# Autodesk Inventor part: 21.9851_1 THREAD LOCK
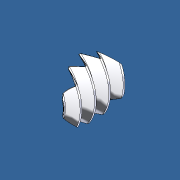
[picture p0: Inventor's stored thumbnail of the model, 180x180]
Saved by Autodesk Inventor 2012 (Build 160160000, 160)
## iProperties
Created: 2014-01
Part Number: 21.9851_1 THREAD LOCK
Material: Nylon-6/6
Document SubType Name: Modeling
Designer: Admin
Density: 1.13 g/cm^3
Mass: 0.000208576 g
Surface Area: 0.273354 cm^2
Volume: 0.00018458 cm^3
Author: Admin
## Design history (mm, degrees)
node "90251A1621"
node "Base1"
body "Solid1"
